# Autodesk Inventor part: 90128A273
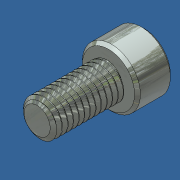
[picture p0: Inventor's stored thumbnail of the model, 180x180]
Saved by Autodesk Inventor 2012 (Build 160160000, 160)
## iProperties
Created: 2014-04
Part Number: 90128A273
Material: Steel
Document SubType Name: Modeling
Designer: Admin
Density: 7.85 g/cm^3
Mass: 12.1919 g
Surface Area: 12.6734 cm^2
Volume: 1.55311 cm^3
Translation Standard: STEP AP203
FileName: 90128A273.step
PreProcessor: SolidWorks 2013
PostProcessor: Build: 160, Release: 2012 RTM - Date: Tue 03/01/2011
Sent Units: inch
Uncertainty: 1e-05
Author: Admin
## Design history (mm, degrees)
node "90128A2731"
node "Base1"
body "Solid1"
